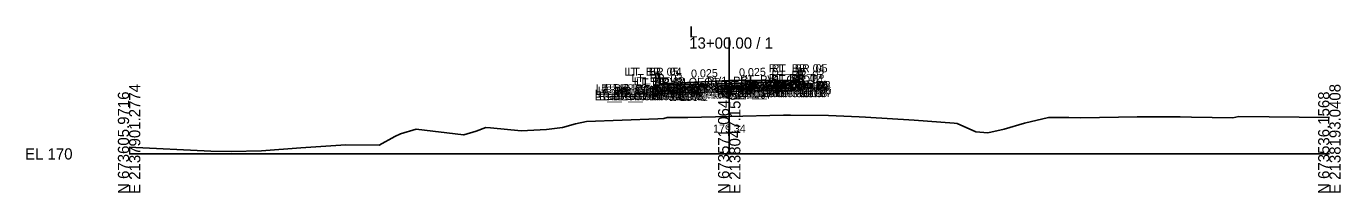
# Model space of a CAD drawing. Extents: x -26 to 5503, y -10 to 7033.
# Drawn here: x -25.7 to 302.8, y 3990.3 to 4031.9 of the extents above; entities that cross this region are included whole.
import ezdxf

# ---------------------------------------------------------------- set-up
doc = ezdxf.new("R2010")
doc.units = 0
for name, color, linetype in [('Default', 7, 'Continuous'), ('Exist Cross Section Cell', 7, 'Continuous'), ('Exist XS Center Line Elevation Label', 7, 'Continuous'), ('Exist XS Ground Line', 7, 'Continuous'), ('Prop CMT Concrete Structures', 7, 'Continuous'), ('Prop XS SE Text', 7, 'Continuous')]:
    doc.layers.add(name, color=color, linetype=linetype)

msp = doc.modelspace()

# ---------------------------------------------------------------- linework, layer by layer
at = {"layer": 'Exist Cross Section Cell'}
for p, q in [((150, 4000), (150, 4029.1)), ((0, 4000), (150, 4000)), ((150, 4000), (300, 4000))]:
    msp.add_line(p, q, dxfattribs=at)
at = {"layer": 'Exist XS Ground Line'}
for p, q in [((114.36, 4008.08), (132.14, 4008.8)), ((132.14, 4008.8), (133.69, 4008.89)), ((133.69, 4008.89), (134.45, 4009.12)), ((134.45, 4009.12), (139.68, 4009.08)), ((139.68, 4009.08), (150, 4009.34)), ((150, 4009.34), (163.55, 4009.67)), ((163.55, 4009.67), (165.34, 4009.7)), ((165.34, 4009.7), (174.84, 4009.62)), ((174.84, 4009.62), (182.5, 4009.24)), ((182.5, 4009.24), (184.1, 4009.17)), ((184.1, 4009.17), (196.24, 4008.43)), ((196.24, 4008.43), (206.21, 4007.7)), ((223.82, 4007.69), (229.77, 4009.07)), ((229.77, 4009.07), (234.91, 4009.07)), ((234.91, 4009.07), (237.88, 4009.03)), ((237.88, 4009.03), (251.97, 4009.27)), ((251.97, 4009.27), (255.66, 4009.26)), ((255.66, 4009.26), (258.78, 4009.25)), ((258.78, 4009.25), (260.25, 4009.25)), ((260.25, 4009.25), (262.69, 4009.26)), ((262.69, 4009.26), (265.57, 4009.2)), ((265.57, 4009.2), (275.88, 4009.06)), ((275.88, 4009.06), (277.34, 4009.34)), ((277.34, 4009.34), (300, 4009.08)), ((66.41, 4004.36), (67.84, 4004.98)), ((67.84, 4004.98), (71.77, 4006.2)), ((71.77, 4006.2), (83.56, 4004.8)), ((83.67, 4004.79), (86.78, 4005.66)), ((86.78, 4005.66), (89.19, 4006.61)), ((89.19, 4006.61), (90.36, 4006.55)), ((90.36, 4006.55), (97.97, 4005.8)), ((97.97, 4005.8), (104.37, 4006.07)), ((104.37, 4006.07), (108.33, 4006.64)), ((108.33, 4006.64), (111.56, 4007.52)), ((111.56, 4007.52), (114.36, 4008.08)), ((206.21, 4007.7), (206.96, 4007.64)), ((206.96, 4007.64), (211.65, 4005.48)), ((211.65, 4005.48), (214.66, 4005.24)), ((214.66, 4005.24), (218.76, 4006.17)), ((218.76, 4006.17), (223.82, 4007.69)), ((0, 4001.66), (20.46, 4000.69)), ((33.06, 4000.81), (42.9, 4001.56)), ((42.9, 4001.56), (54.19, 4002.26)), ((54.19, 4002.26), (62.51, 4002.16)), ((62.51, 4002.16), (66.41, 4004.36)), ((83.56, 4004.8), (83.67, 4004.79)), ((20.46, 4000.69), (25.53, 4000.6)), ((25.53, 4000.6), (33.06, 4000.81))]:
    msp.add_line(p, q, dxfattribs=at)
at = {"layer": 'Prop CMT Concrete Structures'}
for p, q in [((131.67, 4017.5), (131.69, 4020.06)), ((132.54, 4020.09), (131.69, 4020.06)), ((132.54, 4020.09), (132.69, 4017.53)), ((165.33, 4018), (162.32, 4017.93)), ((165.34, 4017.75), (165.33, 4018)), ((168.37, 4018.08), (165.36, 4018)), ((165.39, 4018.01), (165.4, 4017.75)), ((167.31, 4018.4), (167.33, 4020.96)), ((167.32, 4018.05), (167.31, 4018.4)), ((168.19, 4020.98), (167.33, 4020.96)), ((168.19, 4020.98), (168.34, 4018.42)), ((168.35, 4018.08), (168.34, 4018.25)), ((168.37, 4018.08), (168.43, 4018.02)), ((168.48, 4016.1), (168.43, 4018.02)), ((131.66, 4017.16), (131.59, 4017.1)), ((131.64, 4015.18), (131.59, 4017.1)), ((131.64, 4015.18), (131.71, 4015.11)), ((134.63, 4017.24), (131.66, 4017.16)), ((131.68, 4017.16), (131.67, 4017.5)), ((131.71, 4015.11), (134.65, 4015.19)), ((132.7, 4017.19), (132.69, 4017.53)), ((134.64, 4016.98), (134.61, 4016.95)), ((134.61, 4016.95), (134.61, 4016.7)), ((134.68, 4016.64), (134.61, 4016.7)), ((134.64, 4016.98), (134.63, 4017.24)), ((134.65, 4015.19), (134.71, 4015.25)), ((134.66, 4017.24), (134.66, 4017.24)), ((134.68, 4016.64), (134.74, 4016.71)), ((134.71, 4015.25), (134.68, 4016.64)), ((134.71, 4015.25), (134.68, 4016.64)), ((137.7, 4017.31), (134.7, 4017.24)), ((134.7, 4017.24), (134.7, 4016.98)), ((134.7, 4016.98), (134.74, 4016.95)), ((134.71, 4015.25), (134.78, 4015.19)), ((134.74, 4016.71), (134.74, 4016.95)), ((134.78, 4015.19), (137.72, 4015.26)), ((137.71, 4017.06), (137.68, 4017.02)), ((137.68, 4017.02), (137.68, 4016.78)), ((137.75, 4016.72), (137.68, 4016.78)), ((137.71, 4017.06), (137.7, 4017.31)), ((137.72, 4015.26), (137.78, 4015.33)), ((137.73, 4017.31), (137.73, 4017.31)), ((137.73, 4017.31), (137.73, 4017.31)), ((137.75, 4016.72), (137.81, 4016.78)), ((137.78, 4015.33), (137.75, 4016.72)), ((137.78, 4015.33), (137.75, 4016.72)), ((140.77, 4017.39), (137.77, 4017.31)), ((137.77, 4017.31), (137.77, 4017.06)), ((137.77, 4017.06), (137.81, 4017.03)), ((137.78, 4015.33), (137.85, 4015.27)), ((137.81, 4016.78), (137.81, 4017.03)), ((137.85, 4015.27), (140.79, 4015.34)), ((140.78, 4017.13), (140.75, 4017.1)), ((140.75, 4017.1), (140.75, 4016.86)), ((140.82, 4016.79), (140.75, 4016.86)), ((140.78, 4017.13), (140.77, 4017.39)), ((140.79, 4015.34), (140.86, 4015.41)), ((140.8, 4017.39), (140.8, 4017.39)), ((140.8, 4017.39), (140.8, 4017.39)), ((140.82, 4016.79), (140.88, 4016.86)), ((140.85, 4015.41), (140.82, 4016.79)), ((140.85, 4015.41), (140.82, 4016.79)), ((143.84, 4017.47), (140.84, 4017.39)), ((140.84, 4017.39), (140.84, 4017.14)), ((140.84, 4017.14), (140.88, 4017.1)), ((140.85, 4015.41), (140.92, 4015.34)), ((140.88, 4016.86), (140.88, 4017.1)), ((140.92, 4015.34), (143.86, 4015.42)), ((143.85, 4017.21), (143.82, 4017.18)), ((143.82, 4017.18), (143.82, 4016.93)), ((143.89, 4016.87), (143.82, 4016.93)), ((143.85, 4017.21), (143.84, 4017.47)), ((143.86, 4015.42), (143.93, 4015.48)), ((143.87, 4017.47), (143.87, 4017.47)), ((143.88, 4017.47), (143.88, 4017.47)), ((143.89, 4016.87), (143.95, 4016.94)), ((143.92, 4015.48), (143.89, 4016.87)), ((143.93, 4015.48), (143.89, 4016.87)), ((146.91, 4017.54), (143.91, 4017.47)), ((143.91, 4017.47), (143.91, 4017.21)), ((143.91, 4017.21), (143.95, 4017.18)), ((143.93, 4015.48), (143.99, 4015.42)), ((143.95, 4016.94), (143.95, 4017.18)), ((143.99, 4015.42), (146.93, 4015.5)), ((146.92, 4017.29), (146.89, 4017.25)), ((146.89, 4017.25), (146.9, 4017.01)), ((146.96, 4016.95), (146.9, 4017.01)), ((146.92, 4017.29), (146.91, 4017.54)), ((146.93, 4015.5), (147, 4015.56)), ((146.95, 4017.54), (146.95, 4017.54)), ((146.95, 4017.54), (146.95, 4017.54)), ((146.96, 4016.95), (147.02, 4017.01)), ((147, 4015.56), (146.96, 4016.95)), ((147, 4015.56), (146.96, 4016.95)), ((149.99, 4017.62), (146.98, 4017.55)), ((146.98, 4017.55), (146.99, 4017.29)), ((146.99, 4017.29), (147.02, 4017.26)), ((147, 4015.56), (147.06, 4015.5)), ((147.02, 4017.01), (147.02, 4017.26)), ((147.06, 4015.5), (150.01, 4015.57)), ((149.99, 4017.36), (149.96, 4017.33)), ((149.96, 4017.33), (149.97, 4017.09)), ((150.03, 4017.02), (149.97, 4017.09)), ((149.99, 4017.36), (149.99, 4017.62)), ((150.01, 4015.57), (150.07, 4015.64)), ((150.02, 4017.62), (150.02, 4017.62)), ((150.02, 4017.62), (150.02, 4017.62)), ((150.03, 4017.02), (150.1, 4017.09)), ((150.07, 4015.64), (150.03, 4017.02)), ((150.07, 4015.64), (150.03, 4017.02)), ((151.55, 4017.66), (150.05, 4017.62)), ((150.05, 4017.62), (150.06, 4017.37)), ((150.06, 4017.37), (150.09, 4017.33)), ((150.07, 4015.64), (150.13, 4015.58)), ((150.1, 4017.09), (150.09, 4017.33)), ((150.13, 4015.58), (151.6, 4015.61)), ((153.05, 4017.7), (151.55, 4017.66)), ((151.6, 4015.61), (153.07, 4015.65)), ((153.05, 4017.44), (153.02, 4017.41)), ((153.02, 4017.41), (153.03, 4017.16)), ((153.1, 4017.1), (153.03, 4017.16)), ((153.05, 4017.44), (153.05, 4017.7)), ((153.07, 4015.65), (153.13, 4015.71)), ((153.08, 4017.7), (153.08, 4017.7)), ((153.09, 4017.1), (153.16, 4017.17)), ((153.13, 4015.71), (153.09, 4017.1)), ((153.13, 4015.71), (153.1, 4017.1)), ((156.12, 4017.77), (153.11, 4017.7)), ((153.11, 4017.7), (153.12, 4017.44)), ((153.12, 4017.44), (153.15, 4017.41)), ((153.13, 4015.71), (153.19, 4015.65)), ((153.16, 4017.17), (153.15, 4017.41)), ((153.19, 4015.65), (156.14, 4015.73)), ((153.19, 4015.65), (156.14, 4015.73)), ((156.12, 4017.52), (156.09, 4017.48)), ((156.09, 4017.48), (156.1, 4017.24)), ((156.17, 4017.18), (156.1, 4017.24)), ((156.12, 4017.52), (156.12, 4017.77)), ((156.14, 4015.73), (156.2, 4015.79)), ((156.15, 4017.77), (156.15, 4017.77)), ((156.16, 4017.18), (156.23, 4017.24)), ((156.2, 4015.79), (156.16, 4017.18)), ((156.2, 4015.79), (156.17, 4017.18)), ((159.19, 4017.85), (156.18, 4017.78)), ((156.18, 4017.78), (156.19, 4017.52)), ((156.19, 4017.52), (156.22, 4017.49)), ((156.2, 4015.79), (156.26, 4015.73)), ((156.23, 4017.24), (156.22, 4017.49)), ((156.26, 4015.73), (159.21, 4015.8)), ((156.26, 4015.73), (159.21, 4015.8)), ((159.19, 4017.59), (159.16, 4017.56)), ((159.16, 4017.56), (159.17, 4017.32)), ((159.24, 4017.25), (159.17, 4017.32)), ((159.19, 4017.59), (159.19, 4017.85)), ((159.21, 4015.8), (159.27, 4015.87)), ((159.22, 4017.85), (159.22, 4017.85)), ((159.23, 4017.25), (159.3, 4017.32)), ((159.27, 4015.87), (159.23, 4017.25)), ((159.27, 4015.87), (159.24, 4017.25)), ((162.26, 4017.93), (159.25, 4017.85)), ((159.25, 4017.85), (159.26, 4017.6)), ((159.26, 4017.6), (159.29, 4017.56)), ((159.27, 4015.87), (159.33, 4015.81)), ((159.3, 4017.32), (159.29, 4017.56)), ((159.33, 4015.81), (162.28, 4015.88)), ((159.33, 4015.81), (162.28, 4015.88)), ((162.26, 4017.67), (162.23, 4017.64)), ((162.23, 4017.64), (162.24, 4017.39)), ((162.31, 4017.33), (162.24, 4017.39)), ((162.26, 4017.67), (162.26, 4017.93)), ((162.28, 4015.88), (162.34, 4015.94)), ((162.29, 4017.93), (162.29, 4017.93)), ((162.3, 4017.33), (162.37, 4017.4)), ((162.34, 4015.94), (162.3, 4017.33)), ((162.34, 4015.94), (162.31, 4017.33)), ((162.32, 4017.93), (162.33, 4017.67)), ((162.33, 4017.67), (162.36, 4017.64)), ((162.34, 4015.94), (162.4, 4015.88)), ((162.37, 4017.4), (162.36, 4017.64)), ((162.4, 4015.88), (165.35, 4015.96)), ((162.4, 4015.88), (165.35, 4015.96)), ((165.34, 4017.75), (165.3, 4017.72)), ((165.3, 4017.72), (165.31, 4017.47)), ((165.38, 4017.41), (165.31, 4017.47)), ((165.35, 4015.96), (165.41, 4016.02)), ((165.37, 4017.41), (165.44, 4017.47)), ((165.41, 4016.02), (165.37, 4017.41)), ((165.41, 4016.02), (165.38, 4017.41)), ((165.4, 4017.75), (165.43, 4017.72)), ((165.41, 4016.02), (165.47, 4015.96)), ((165.44, 4017.47), (165.43, 4017.72)), ((165.47, 4015.96), (168.42, 4016.03)), ((168.42, 4016.03), (168.48, 4016.1))]:
    msp.add_line(p, q, dxfattribs=at)
msp.add_lwpolyline([(132.69, 4017.53), (150, 4018.31), (167.31, 4018.4), (167.32, 4018.05), (132.7, 4017.19)], close=True, dxfattribs=at)
msp.add_lwpolyline([(168.35, 4018.08), (168.34, 4018.42)], dxfattribs=at)
for centre in [(132.47, 4016.16), (133.84, 4016.19), (135.54, 4016.23), (136.91, 4016.27), (138.61, 4016.31), (139.98, 4016.35), (141.68, 4016.39), (143.05, 4016.42), (144.75, 4016.47), (146.12, 4016.5), (147.83, 4016.54), (149.19, 4016.58), (150.9, 4016.62), (152.25, 4016.65), (153.96, 4016.7), (155.32, 4016.73), (157.03, 4016.77), (158.39, 4016.81), (160.1, 4016.85), (161.46, 4016.88), (163.17, 4016.93), (164.53, 4016.96), (166.24, 4017), (167.6, 4017.04)]:
    msp.add_circle(centre, 0.512, dxfattribs=at)

# ---------------------------------------------------------------- texts
at = {"layer": 'Default'}
for s, height, p in [('LT_ BR_05', 2, (123.82, 4019.55)), ('LT_ BR_04', 2, (124.56, 4019.55)), ('RT_ BR_04', 2, (159.87, 4020.4)), ('RT_ BR_05', 2, (160.61, 4020.4)), ('LT_BR_03', 2, (125.54, 4017.97)), ('LT_BR_02', 2, (126.13, 4017.13)), ('LT_BR_01', 2, (126.71, 4016.88)), ('LT_PV1_OEOT', 2, (128.74, 4017.01)), ('PV1_PGL', 2, (144.47, 4017.31)), ('RT_BR_Girder Out 14', 2, (147.85, 4016.17)), ('RT_BR_Girder Out 01', 2, (148.6, 4016.19)), ('RT_BR_Girder Out 02', 2, (148.87, 4016.21)), ('RT_PV1_OEOT', 2, (152.69, 4017.61)), ('RT_BR_07', 2, (155.01, 4016.11)), ('RT_BR_02', 2, (159.93, 4017.98)), ('RT_BR_01', 2, (160.49, 4017.73)), ('RT_BR_03', 2, (160.52, 4018.81)), ('RT_BR_06', 2, (161.38, 4016.27)), ('LT_BR_Girder Out 06', 2, (116.36, 4014.09)), ('LT_BR_Girder Out 07', 2, (116.41, 4013.43)), ('LT_BR_Girder Out 02', 2, (116.66, 4015.4)), ('LT_BR_Girder Out 03', 2, (116.66, 4014.76)), ('LT_BR_Girder Out 05', 2, (117.16, 4014.84)), ('LT_BR_Girder Out 04', 2, (117.16, 4014.26)), ('LT_BR_Girder Out 08', 2, (117.49, 4013.43)), ('LT_BR_Girder Out 01', 2, (118.06, 4015.43)), ('LT_BR_Girder Out 12', 2, (118.47, 4014.26)), ('LT_BR_Girder Out 09', 2, (118.58, 4013.43)), ('LT_BR_Girder Out 14', 2, (118.97, 4015.45)), ('LT_BR_Girder Out 13', 2, (118.97, 4014.76)), ('LT_BR_Girder Out 11', 2, (119.04, 4014.84)), ('LT_BR_Girder Out 10', 2, (119.14, 4014.09)), ('LT_BR_06', 2, (124.59, 4015.35)), ('LT_BR_07', 2, (131.06, 4015.51)), ('LT_BR_Girder Mid 06', 2, (132.05, 4014.47)), ('LT_BR_Girder Mid 07', 2, (132.1, 4013.81)), ('LT_BR_Girder Mid 02', 2, (132.35, 4015.79)), ('LT_BR_Girder Mid 03', 2, (132.35, 4015.14)), ('LT_BR_Girder Mid 05', 2, (132.85, 4015.22)), ('LT_BR_Girder Mid 04', 2, (132.85, 4014.64)), ('RT_BR_Girder Mid 05', 2, (133.47, 4015.22)), ('RT_BR_Girder Mid 04', 2, (133.47, 4014.64)), ('RT_BR_Girder Mid 02', 2, (133.97, 4015.83)), ('RT_BR_Girder Mid 03', 2, (133.97, 4015.14)), ('RT_BR_Girder Mid 06', 2, (134.17, 4014.47)), ('RT_BR_Girder Mid 07', 2, (134.22, 4013.81)), ('BR_Girder Mid 08', 2, (135.87, 4013.81)), ('BR_PGL', 2, (144.83, 4015.81)), ('RT_BR_Girder Out 09', 2, (146.95, 4014.19)), ('RT_BR_Girder Out 10', 2, (147.52, 4014.86)), ('RT_BR_Girder Out 13', 2, (147.85, 4015.52)), ('RT_BR_Girder Out 08', 2, (148.03, 4014.19)), ('RT_BR_Girder Out 12', 2, (148.35, 4015.02)), ('RT_BR_Girder Out 05', 2, (148.37, 4015.61)), ('RT_BR_Girder Out 04', 2, (148.37, 4015.02)), ('RT_BR_Girder Out 03', 2, (148.87, 4015.52)), ('RT_BR_Girder Out 11', 2, (148.91, 4015.61)), ('RT_BR_Girder Out 06', 2, (149.07, 4014.86)), ('RT_BR_Girder Out 07', 2, (149.12, 4014.19)), ('-', 0.0001, (0, 4000))]:
    msp.add_text(s, height=height, dxfattribs=at).set_placement(p)
at = {"layer": 'Exist Cross Section Cell'}
for s, p in [('L', (140, 4029.1)), ('13+00.00 / 1', (140, 4026.3)), ('EL 170', (-26, 3998.6))]:
    msp.add_text(s, height=2.8, dxfattribs=at).set_placement(p)
for s, p in [('N 673605.9716', (0, 3990)), ('E 2137901.2774', (2.8, 3990)), ('N 673571.0642', (150, 3990)), ('E 2138047.1591', (152.8, 3990)), ('N 673536.1568', (300, 3990)), ('E 2138193.0408', (302.8, 3990))]:
    msp.add_text(s, height=2.8, rotation=90, dxfattribs=at).set_placement(p)
at = {"layer": 'Exist XS Center Line Elevation Label'}
msp.add_text('179.34', height=2, dxfattribs=at).set_placement((145.96, 4005.34))
at = {"layer": 'Prop XS SE Text'}
for p in [(152.48, 4019.37), (140.48, 4019.07)]:
    msp.add_text('0.025', height=2, rotation=1.4321, dxfattribs=at).set_placement(p)

doc.saveas('drawing.dxf')
